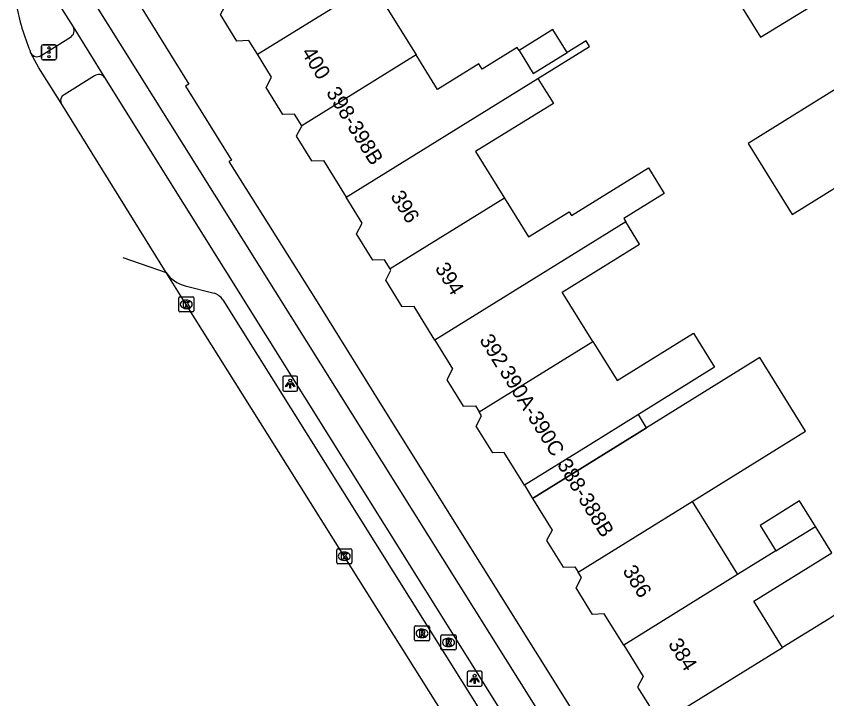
# Model space of a CAD drawing. Extents: x 160026 to 161302, y 384757 to 385701.
# Drawn here: x 160026.7 to 160080.6, y 385265.1 to 385310.5 of the extents above; entities that cross this region are included whole.
import ezdxf

# ---------------------------------------------------------------- set-up
doc = ezdxf.new("R2010")
doc.units = 0
for name, color, linetype in [('IMGEO_Fietspad_gesloten', 7, 'Continuous'), ('IMGEO_Kolk', 7, 'Continuous'), ('IMGEO_Lichtpunt', 7, 'Continuous'), ('IMGEO_Pand', 7, 'Continuous'), ('IMGEO_Pand_nummerreeks', 7, 'Continuous'), ('IMGEO_Pand_overbouw', 7, 'Continuous'), ('IMGEO_Parkeervlak_open', 7, 'Continuous'), ('IMGEO_Rijbaan_regionaal_gesloten', 7, 'Continuous'), ('IMGEO_Rioolput', 7, 'Continuous'), ('IMGEO_Verkeersregelinstallatiepaal', 7, 'Continuous'), ('IMGEO_Voetpad_open', 7, 'Continuous')]:
    doc.layers.add(name, color=color, linetype=linetype)

msp = doc.modelspace()

# ---------------------------------------------------------------- linework, layer by layer
at = {"layer": 'IMGEO_Fietspad_gesloten'}
for points in [[(160123.778, 385164.743), (160087.491, 385222.641), (160070.35, 385250), (160030.703, 385313.283), (160030.2, 385314.143)], [(160028.321, 385313.156), (160030.444, 385309.783)], [(160030.444, 385309.783), (160032.543, 385306.417)], [(160032.543, 385306.417), (160061.871, 385259.541), (160067.835, 385250), (160085.578, 385221.627), (160124.152, 385160.161), (160150.574, 385117.95), (160168.154, 385089.798)]]:
    msp.add_lwpolyline(points, dxfattribs=at)
at = {"layer": 'IMGEO_Kolk'}
for p, q in [((160037.477, 385290.896), (160037.477, 385291.748)), ((160037.552, 385291.822), (160038.404, 385291.822)), ((160038.478, 385291.748), (160038.478, 385290.896)), ((160037.965, 385291.602), (160037.99, 385291.602)), ((160038.404, 385290.822), (160037.552, 385290.822)), ((160037.988, 385291.042), (160037.963, 385291.042)), ((160047.987, 385274.137), (160047.987, 385274.989)), ((160048.062, 385275.063), (160048.914, 385275.063)), ((160048.988, 385274.989), (160048.988, 385274.137)), ((160048.475, 385274.843), (160048.5, 385274.843)), ((160048.914, 385274.063), (160048.062, 385274.063)), ((160048.498, 385274.283), (160048.473, 385274.283))]:
    msp.add_line(p, q, dxfattribs=at)
for points in [[(160037.477, 385290.896), (160037.477, 385291.748)], [(160037.552, 385291.822), (160038.404, 385291.822)], [(160038.478, 385291.748), (160038.478, 385290.896)], [(160037.798, 385291.522), (160037.921, 385291.522), (160037.921, 385291.371), (160038.051, 385291.522), (160038.215, 385291.522), (160038.069, 385291.371), (160038.222, 385291.122), (160038.07, 385291.122), (160037.985, 385291.286), (160037.921, 385291.219), (160037.921, 385291.122), (160037.798, 385291.122), (160037.798, 385291.522)], [(160038.404, 385290.822), (160037.552, 385290.822)], [(160047.987, 385274.137), (160047.987, 385274.989)], [(160048.062, 385275.063), (160048.914, 385275.063)], [(160048.988, 385274.989), (160048.988, 385274.137)], [(160048.308, 385274.763), (160048.431, 385274.763), (160048.431, 385274.612), (160048.561, 385274.763), (160048.725, 385274.763), (160048.579, 385274.612), (160048.732, 385274.363), (160048.58, 385274.363), (160048.495, 385274.527), (160048.431, 385274.46), (160048.431, 385274.363), (160048.308, 385274.363), (160048.308, 385274.763)], [(160048.914, 385274.063), (160048.062, 385274.063)]]:
    msp.add_lwpolyline(points, dxfattribs=at)
for centre, start, end in [((160037.554, 385291.746), 91.552, 178.448), ((160037.554, 385291.746), 91.552, 178.448), ((160038.402, 385291.746), 1.552, 88.448), ((160038.402, 385291.746), 1.552, 88.448), ((160037.554, 385290.898), 181.552, 268.448), ((160037.554, 385290.898), 181.552, 268.448), ((160038.402, 385290.898), 271.552, 358.448), ((160038.402, 385290.898), 271.552, 358.448), ((160048.064, 385274.987), 91.552, 178.448), ((160048.064, 385274.987), 91.552, 178.448), ((160048.912, 385274.987), 1.552, 88.448), ((160048.912, 385274.987), 1.552, 88.448), ((160048.064, 385274.139), 181.552, 268.448), ((160048.064, 385274.139), 181.552, 268.448), ((160048.912, 385274.139), 271.552, 358.448), ((160048.912, 385274.139), 271.552, 358.448)]:
    msp.add_arc(centre, 0.0765, start, end, dxfattribs=at)
for centre, major_axis, ratio, start_param, end_param in [((160037.964, 385291.322), (-0.387, 0.002), 0.722429, 4.712389, 7.853982), ((160037.989, 385291.322), (-0.39, 0.002), 0.717154, 1.570796, 4.712389), ((160048.474, 385274.563), (-0.387, 0.002), 0.722429, 4.712389, 7.853982), ((160048.499, 385274.563), (-0.39, 0.002), 0.717154, 1.570796, 4.712389)]:
    msp.add_ellipse(centre, major_axis=major_axis, ratio=ratio, start_param=start_param, end_param=end_param, dxfattribs=at)
at = {"layer": 'IMGEO_Lichtpunt'}
for p, q in [((160044.394, 385286.45), (160044.394, 385285.643)), ((160044.394, 385286.45), (160044.394, 385285.643)), ((160045.296, 385286.545), (160044.488, 385286.545)), ((160045.296, 385286.545), (160044.488, 385286.545)), ((160045.39, 385285.643), (160045.39, 385286.45)), ((160045.39, 385285.643), (160045.39, 385286.45)), ((160044.488, 385285.549), (160045.296, 385285.549)), ((160044.488, 385285.549), (160045.296, 385285.549)), ((160057.572, 385266.905), (160056.764, 385266.905)), ((160057.572, 385266.905), (160056.764, 385266.905)), ((160056.67, 385266.81), (160056.67, 385266.003)), ((160056.67, 385266.81), (160056.67, 385266.003)), ((160057.666, 385266.003), (160057.666, 385266.81)), ((160057.666, 385266.003), (160057.666, 385266.81)), ((160056.764, 385265.909), (160057.572, 385265.909)), ((160056.764, 385265.909), (160057.572, 385265.909))]:
    msp.add_line(p, q, dxfattribs=at)
for points in [[(160044.768, 385286.114), (160044.807, 385286.086), (160044.619, 385285.824), (160044.581, 385285.851), (160044.768, 385286.114)], [(160044.87, 385286.066), (160044.917, 385286.066), (160044.917, 385285.744), (160044.87, 385285.744), (160044.87, 385286.066)], [(160044.98, 385286.086), (160045.018, 385286.113), (160045.205, 385285.851), (160045.166, 385285.823), (160044.98, 385286.086)], [(160057.044, 385266.474), (160057.083, 385266.446), (160056.895, 385266.184), (160056.857, 385266.211), (160057.044, 385266.474)], [(160057.146, 385266.426), (160057.193, 385266.426), (160057.193, 385266.104), (160057.146, 385266.104), (160057.146, 385266.426)], [(160057.256, 385266.446), (160057.294, 385266.473), (160057.481, 385266.211), (160057.442, 385266.183), (160057.256, 385266.446)]]:
    msp.add_lwpolyline(points, dxfattribs=at)
for centre in [(160044.893, 385286.248), (160057.169, 385266.608)]:
    msp.add_circle(centre, 0.0994, dxfattribs=at)
for centre, start, end in [((160044.488, 385286.45), 90, 180), ((160044.488, 385286.45), 90, 180), ((160045.296, 385286.45), 0, 90), ((160045.296, 385286.45), 0, 90), ((160044.488, 385285.643), 180, 270), ((160044.488, 385285.643), 180, 270), ((160045.296, 385285.643), 270, 0), ((160045.296, 385285.643), 270, 360), ((160056.764, 385266.81), 90, 180), ((160056.764, 385266.81), 90, 180), ((160057.572, 385266.81), 0, 90), ((160057.572, 385266.81), 0, 90), ((160056.764, 385266.003), 180, 270), ((160056.764, 385266.003), 180, 270), ((160057.572, 385266.003), 270, 0), ((160057.572, 385266.003), 270, 360)]:
    msp.add_arc(centre, 0.0946, start, end, dxfattribs=at)
at = {"layer": 'IMGEO_Pand'}
for points in [[(160042.71, 385307.971), (160042.152, 385308.87), (160041.348, 385308.844), (160040.258, 385310.602), (160040.632, 385311.3), (160040.342, 385311.766), (160039.593, 385311.941), (160038.364, 385313.922), (160038.676, 385314.504), (160038.362, 385315.011), (160038.339, 385316.435), (160038.595, 385316.807), (160038.321, 385317.381), (160039.25, 385318.732), (160039.931, 385318.678), (160041.788, 385321.377)], [(160079.033, 385314.298), (160077.982, 385315.993), (160077.737, 385316.388), (160077.51, 385316.754), (160077.227, 385316.578), (160076.797, 385316.312), (160073.131, 385314.037), (160076.198, 385309.096), (160080.576, 385311.813)], [(160042.71, 385307.971), (160050.317, 385312.681)], [(160050.317, 385312.681), (160053.27, 385307.922)], [(160063.326, 385308.085), (160062.383, 385309.604), (160060.128, 385308.205)], [(160060.128, 385308.205), (160060.004, 385308.405), (160057.678, 385306.962), (160057.458, 385307.317), (160054.705, 385305.609), (160053.27, 385307.922)], [(160061.38, 385306.356), (160064.822, 385308.487), (160064.586, 385308.867), (160063.326, 385308.085)], [(160045.658, 385303.21), (160045.176, 385303.987), (160044.4, 385303.963), (160043.29, 385305.752), (160043.659, 385306.441), (160042.71, 385307.971)], [(160053.27, 385307.922), (160045.658, 385303.21)], [(160060.128, 385308.205), (160061.07, 385306.686), (160063.326, 385308.085)], [(160048.612, 385298.453), (160061.38, 385306.356)], [(160061.38, 385306.356), (160061.928, 385305.473), (160062.173, 385305.078), (160062.411, 385304.696), (160059.994, 385303.197), (160057.237, 385301.487), (160059.156, 385298.394)], [(160075.368, 385302.021), (160078.302, 385297.294), (160085.156, 385301.549), (160082.223, 385306.275), (160075.368, 385302.021)], [(160045.658, 385303.21), (160045.284, 385302.512), (160046.308, 385300.861), (160047.101, 385300.887), (160048.612, 385298.453)], [(160059.156, 385298.394), (160060.759, 385295.81), (160063.462, 385297.488), (160063.615, 385297.241), (160068.73, 385300.415), (160069.789, 385298.708), (160067.093, 385297.035), (160067.234, 385296.808)], [(160051.543, 385293.681), (160051.164, 385294.291), (160050.398, 385294.267), (160049.307, 385296.025), (160049.683, 385296.726), (160048.612, 385298.453)], [(160059.156, 385298.394), (160051.543, 385293.681)], [(160067.234, 385296.808), (160054.521, 385288.939)], [(160065.028, 385288.855), (160062.995, 385292.131), (160068.151, 385295.33), (160067.234, 385296.808)], [(160054.521, 385288.939), (160053.136, 385291.171), (160052.356, 385291.146), (160051.249, 385292.929), (160051.602, 385293.586), (160051.543, 385293.681)], [(160065.028, 385288.855), (160066.646, 385286.247), (160071.731, 385289.403), (160072.041, 385288.904), (160073.139, 385287.134), (160068.063, 385283.985), (160064.73, 385281.917), (160060.481, 385279.28), (160059.126, 385281.463), (160058.371, 385281.439), (160057.263, 385283.224), (160057.634, 385283.915), (160057.471, 385284.178)], [(160054.521, 385288.939), (160055.705, 385287.031), (160055.318, 385286.308), (160056.406, 385284.554), (160057.221, 385284.58), (160057.471, 385284.178)], [(160057.471, 385284.178), (160065.028, 385288.855)], [(160071.649, 385278.206), (160079.194, 385282.889), (160076.153, 385287.789), (160068.608, 385283.106), (160065.275, 385281.038), (160061.026, 385278.402), (160062.329, 385276.302), (160061.958, 385275.611), (160063.06, 385273.836), (160063.838, 385273.861), (160064.062, 385273.5)], [(160064.062, 385273.5), (160071.649, 385278.206)], [(160071.649, 385278.206), (160073.616, 385275.036), (160074.67, 385273.337)], [(160079.847, 385276.548), (160078.792, 385278.248), (160076.16, 385276.615), (160077.214, 385274.915)], [(160077.664, 385268.491), (160075.759, 385271.561), (160080.945, 385274.779), (160079.847, 385276.548)], [(160077.214, 385274.915), (160079.847, 385276.548)], [(160077.214, 385274.915), (160074.67, 385273.337)], [(160067.087, 385268.634), (160065.793, 385270.72), (160065.007, 385270.695), (160063.915, 385272.454), (160064.284, 385273.142), (160064.062, 385273.5)], [(160074.67, 385273.337), (160067.087, 385268.634)], [(160085.931, 385266.869), (160089.363, 385268.982), (160089.778, 385269.238), (160089.575, 385269.565), (160088.446, 385271.384), (160085.79, 385270.611), (160082.464, 385268.574), (160081.172, 385270.655), (160080.771, 385270.407), (160077.664, 385268.491)], [(160067.087, 385268.634), (160068.381, 385266.549), (160068.009, 385265.854), (160069.064, 385264.154), (160069.864, 385264.179), (160070.088, 385263.817)], [(160070.088, 385263.817), (160077.664, 385268.491)]]:
    msp.add_lwpolyline(points, dxfattribs=at)
at = {"layer": 'IMGEO_Pand_overbouw'}
msp.add_lwpolyline([(160068.063, 385283.985), (160064.73, 385281.917), (160060.481, 385279.28), (160061.026, 385278.402), (160065.275, 385281.038), (160068.608, 385283.106)], close=True, dxfattribs=at)
at = {"layer": 'IMGEO_Parkeervlak_open'}
for points in [[(160037.895, 385292.557), (160039.825, 385292.077)], [(160040.413, 385291.632), (160066.491, 385250), (160082.398, 385224.605), (160084.808, 385220.758), (160099.16, 385197.845), (160101.17, 385194.648), (160111.679, 385177.874)]]:
    msp.add_lwpolyline(points, dxfattribs=at)
for centre, radius, start, end in [((160038.362, 385294.528), 2.026, 212.2252, 256.6821), ((160039.32, 385290.799), 1.374, 37.3143, 68.4486)]:
    msp.add_arc(centre, radius, start, end, dxfattribs=at)
at = {"layer": 'IMGEO_Rijbaan_regionaal_gesloten'}
for points in [[(160027.643, 385308.035), (160027.581, 385308.183)], [(160029.643, 385304.703), (160028.176, 385307.056), (160027.911, 385307.546), (160027.643, 385308.035)], [(160036.648, 385293.448), (160029.643, 385304.703)], [(160033.754, 385294.437), (160036.648, 385293.448)], [(160123.75, 385154.328), (160114.434, 385169.251), (160103.411, 385186.881), (160092.507, 385204.256), (160081.666, 385221.573), (160070.748, 385239.76), (160064.086, 385250), (160059.264, 385257.412), (160048.487, 385274.563), (160044.011, 385281.7), (160037.977, 385291.321), (160036.648, 385293.448)]]:
    msp.add_lwpolyline(points, dxfattribs=at)
msp.add_arc((160042.453, 385314.287), 16.075, 190.7842, 202.3152, dxfattribs=at)
at = {"layer": 'IMGEO_Rioolput'}
for p, q in [((160053.167, 385269.002), (160053.167, 385269.854)), ((160053.242, 385269.928), (160054.094, 385269.928)), ((160053.655, 385269.708), (160053.68, 385269.708)), ((160054.168, 385269.854), (160054.168, 385269.002)), ((160053.678, 385269.148), (160053.653, 385269.148)), ((160054.929, 385268.401), (160054.929, 385269.253)), ((160055.004, 385269.327), (160055.856, 385269.327)), ((160055.417, 385269.107), (160055.442, 385269.107)), ((160055.93, 385269.253), (160055.93, 385268.401)), ((160054.094, 385268.928), (160053.242, 385268.928)), ((160055.44, 385268.547), (160055.415, 385268.547)), ((160055.856, 385268.327), (160055.004, 385268.327))]:
    msp.add_line(p, q, dxfattribs=at)
for points in [[(160053.167, 385269.002), (160053.167, 385269.854)], [(160053.242, 385269.928), (160054.094, 385269.928)], [(160053.756, 385269.626), (160053.504, 385269.628), (160053.504, 385269.228)], [(160053.682, 385269.547), (160053.628, 385269.547), (160053.628, 385269.466)], [(160054.168, 385269.854), (160054.168, 385269.002)], [(160053.504, 385269.228), (160053.628, 385269.228), (160053.628, 385269.39), (160053.639, 385269.39)], [(160053.628, 385269.466), (160053.68, 385269.466)], [(160053.686, 385269.361), (160053.757, 385269.228), (160053.897, 385269.228), (160053.832, 385269.354)], [(160054.929, 385268.401), (160054.929, 385269.253)], [(160055.004, 385269.327), (160055.856, 385269.327)], [(160055.518, 385269.025), (160055.266, 385269.027), (160055.266, 385268.627)], [(160055.93, 385269.253), (160055.93, 385268.401)], [(160054.094, 385268.928), (160053.242, 385268.928)], [(160055.266, 385268.627), (160055.39, 385268.627), (160055.39, 385268.789), (160055.401, 385268.789)], [(160055.444, 385268.946), (160055.39, 385268.946), (160055.39, 385268.865)], [(160055.39, 385268.865), (160055.442, 385268.865)], [(160055.448, 385268.76), (160055.519, 385268.627), (160055.659, 385268.627), (160055.594, 385268.753)], [(160055.856, 385268.327), (160055.004, 385268.327)]]:
    msp.add_lwpolyline(points, dxfattribs=at)
for centre, radius, start, end in [((160053.244, 385269.852), 0.0765, 91.552, 178.448), ((160053.244, 385269.852), 0.0765, 91.552, 178.448), ((160053.688, 385269.451), 0.0964, 77.0061, 93.1865), ((160053.702, 385269.508), 0.0378, 276.6634, 79.6772), ((160053.755, 385269.516), 0.109, 350.3612, 89.416), ((160054.092, 385269.852), 0.0765, 1.552, 88.448), ((160054.092, 385269.852), 0.0765, 1.552, 88.448), ((160053.244, 385269.004), 0.0765, 181.552, 268.448), ((160053.244, 385269.004), 0.0765, 181.552, 268.448), ((160053.638, 385269.337), 0.0533, 26.0293, 88.6989), ((160053.664, 385269.655), 0.19, 274.7715, 282.9687), ((160053.753, 385269.516), 0.112, 277.5842, 350.9817), ((160053.737, 385269.301), 0.108, 29.5134, 73.7905), ((160054.092, 385269.004), 0.0765, 271.552, 358.448), ((160054.092, 385269.004), 0.0765, 271.552, 358.448), ((160055.006, 385269.251), 0.0765, 91.552, 178.448), ((160055.006, 385269.251), 0.0765, 91.552, 178.448), ((160055.517, 385268.915), 0.109, 350.3612, 89.416), ((160055.854, 385269.251), 0.0765, 1.552, 88.448), ((160055.854, 385269.251), 0.0765, 1.552, 88.448), ((160055.4, 385268.736), 0.0533, 26.0293, 88.6989), ((160055.426, 385269.054), 0.19, 274.7715, 282.9687), ((160055.45, 385268.85), 0.0964, 77.0061, 93.1865), ((160055.464, 385268.907), 0.0378, 276.6634, 79.6772), ((160055.515, 385268.915), 0.112, 277.5842, 350.9817), ((160055.499, 385268.7), 0.108, 29.5134, 73.7905), ((160055.006, 385268.403), 0.0765, 181.552, 268.448), ((160055.006, 385268.403), 0.0765, 181.552, 268.448), ((160055.854, 385268.403), 0.0765, 271.552, 358.448), ((160055.854, 385268.403), 0.0765, 271.552, 358.448)]:
    msp.add_arc(centre, radius, start, end, dxfattribs=at)
for centre, major_axis, ratio, start_param, end_param in [((160053.654, 385269.428), (-0.387, 0.002), 0.722429, 4.712389, 7.853982), ((160053.679, 385269.428), (-0.39, 0.002), 0.717154, 1.570796, 4.712389), ((160055.416, 385268.827), (-0.387, 0.002), 0.722429, 4.712389, 7.853982), ((160055.441, 385268.827), (-0.39, 0.002), 0.717154, 1.570796, 4.712389)]:
    msp.add_ellipse(centre, major_axis=major_axis, ratio=ratio, start_param=start_param, end_param=end_param, dxfattribs=at)
at = {"layer": 'IMGEO_Verkeersregelinstallatiepaal'}
for p, q in [((160028.347, 385307.696), (160028.347, 385308.496)), ((160028.347, 385308.496), (160028.347, 385307.696)), ((160028.447, 385308.596), (160029.237, 385308.596)), ((160029.237, 385308.596), (160028.447, 385308.596)), ((160029.337, 385308.496), (160029.337, 385307.696)), ((160029.337, 385307.696), (160029.337, 385308.496)), ((160029.237, 385307.596), (160028.447, 385307.596)), ((160028.447, 385307.596), (160029.237, 385307.596))]:
    msp.add_line(p, q, dxfattribs=at)
for centre in [(160028.842, 385308.386), (160028.842, 385308.096), (160028.842, 385307.806)]:
    msp.add_circle(centre, 0.085, dxfattribs=at)
for centre, start, end in [((160028.447, 385308.496), 90, 180), ((160028.447, 385308.496), 90, 180), ((160029.237, 385308.496), 0, 90), ((160029.237, 385308.496), 360, 90), ((160028.447, 385307.696), 180, 270), ((160028.447, 385307.696), 180, 270), ((160029.237, 385307.696), 270, 0), ((160029.237, 385307.696), 270, 0)]:
    msp.add_arc(centre, 0.1, start, end, dxfattribs=at)
at = {"layer": 'IMGEO_Voetpad_open'}
for points in [[(160032.616, 385314.905), (160038.148, 385305.982), (160037.936, 385305.85), (160040.989, 385300.92), (160040.82, 385300.82), (160046.575, 385291.663), (160050.286, 385285.709), (160050.755, 385284.956), (160071.649, 385251.538), (160071.814, 385251.639), (160072.82, 385250), (160076.049, 385244.741), (160075.929, 385244.686), (160078.326, 385240.862), (160078.493, 385240.928), (160085.88, 385229.102), (160085.619, 385228.915), (160089.292, 385223.094), (160103.458, 385200.92)], [(160028.315, 385307.871), (160030.268, 385309.093)], [(160031.878, 385306.521), (160029.859, 385305.265)]]:
    msp.add_lwpolyline(points, dxfattribs=at)
for centre, radius, start, end in [((160030.014, 385309.525), 0.501, 300.4294, 30.9517), ((160028.061, 385308.29), 0.49, 211.3312, 301.2392), ((160032.162, 385306.157), 0.461, 34.2792, 127.9438), ((160030.055, 385304.867), 0.444, 116.2524, 201.6999)]:
    msp.add_arc(centre, radius, start, end, dxfattribs=at)

# ---------------------------------------------------------------- texts
at = {"layer": 'IMGEO_Pand_nummerreeks'}
for s, rotation, p in [('400', 301.776, (160045.609, 385308.076)), ('398-398B', 301.776, (160047.254, 385305.42)), ('396', 301.776, (160051.532, 385298.516)), ('394', 301.7741, (160054.494, 385293.734)), ('392', 301.7741, (160057.454, 385288.954)), ('390A-390C', 301.9135, (160058.784, 385286.85)), ('388-388B', 301.5812, (160062.623, 385280.668)), ('386', 301.862, (160066.983, 385273.593)), ('384', 301.862, (160070.012, 385268.719))]:
    msp.add_text(s, height=1, rotation=rotation, dxfattribs=at).set_placement(p)

doc.saveas('drawing.dxf')
